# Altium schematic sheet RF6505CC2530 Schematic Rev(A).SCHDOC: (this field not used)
size D; Organization: (this field not used); Address1: (this field not used); Address2: (this field not used); Address3: (this field not used); Address4: (this field not used); DocumentNumber: (this field not used); Revision: (this field not used); SheetNumber: (this field not used); SheetTotal: (this field not used); Date: (this field not used); ApprovedBy: (this field not used); CheckedBy: (this field not used); Author: (this field not used); CompanyName: (this field not used); DrawnBy: (this field not used); Engineer: (this field not used); AFamilypn: 6505; PageSetup: Record=PageOptions|CenterHorizontal=True|CenterVertical=True|PrintScale=0.51|XCorrection=1.00|YCorrection=1.00|PrintKind=0|BorderSize=5000000|LeftOffset=0|BottomOffset=0|Orientation=2|PaperLength=1000|PaperWidth=1000|Scale=100|PaperSource=7|PrintQuality=600|MediaType=1|DitherType=10|PaperKind=11" x 17"|PrintScaleMode=1; Apcbpartnumber: 6505-411; Atitle: RF6505CC2530410 Eval Schem.; Adocumentnumber: 6505-401; Apagenumber: 1; Apagenumbertotal: 1; Arevision: A; Adrawnby: Michael Coolen; Adate: 07/26/11
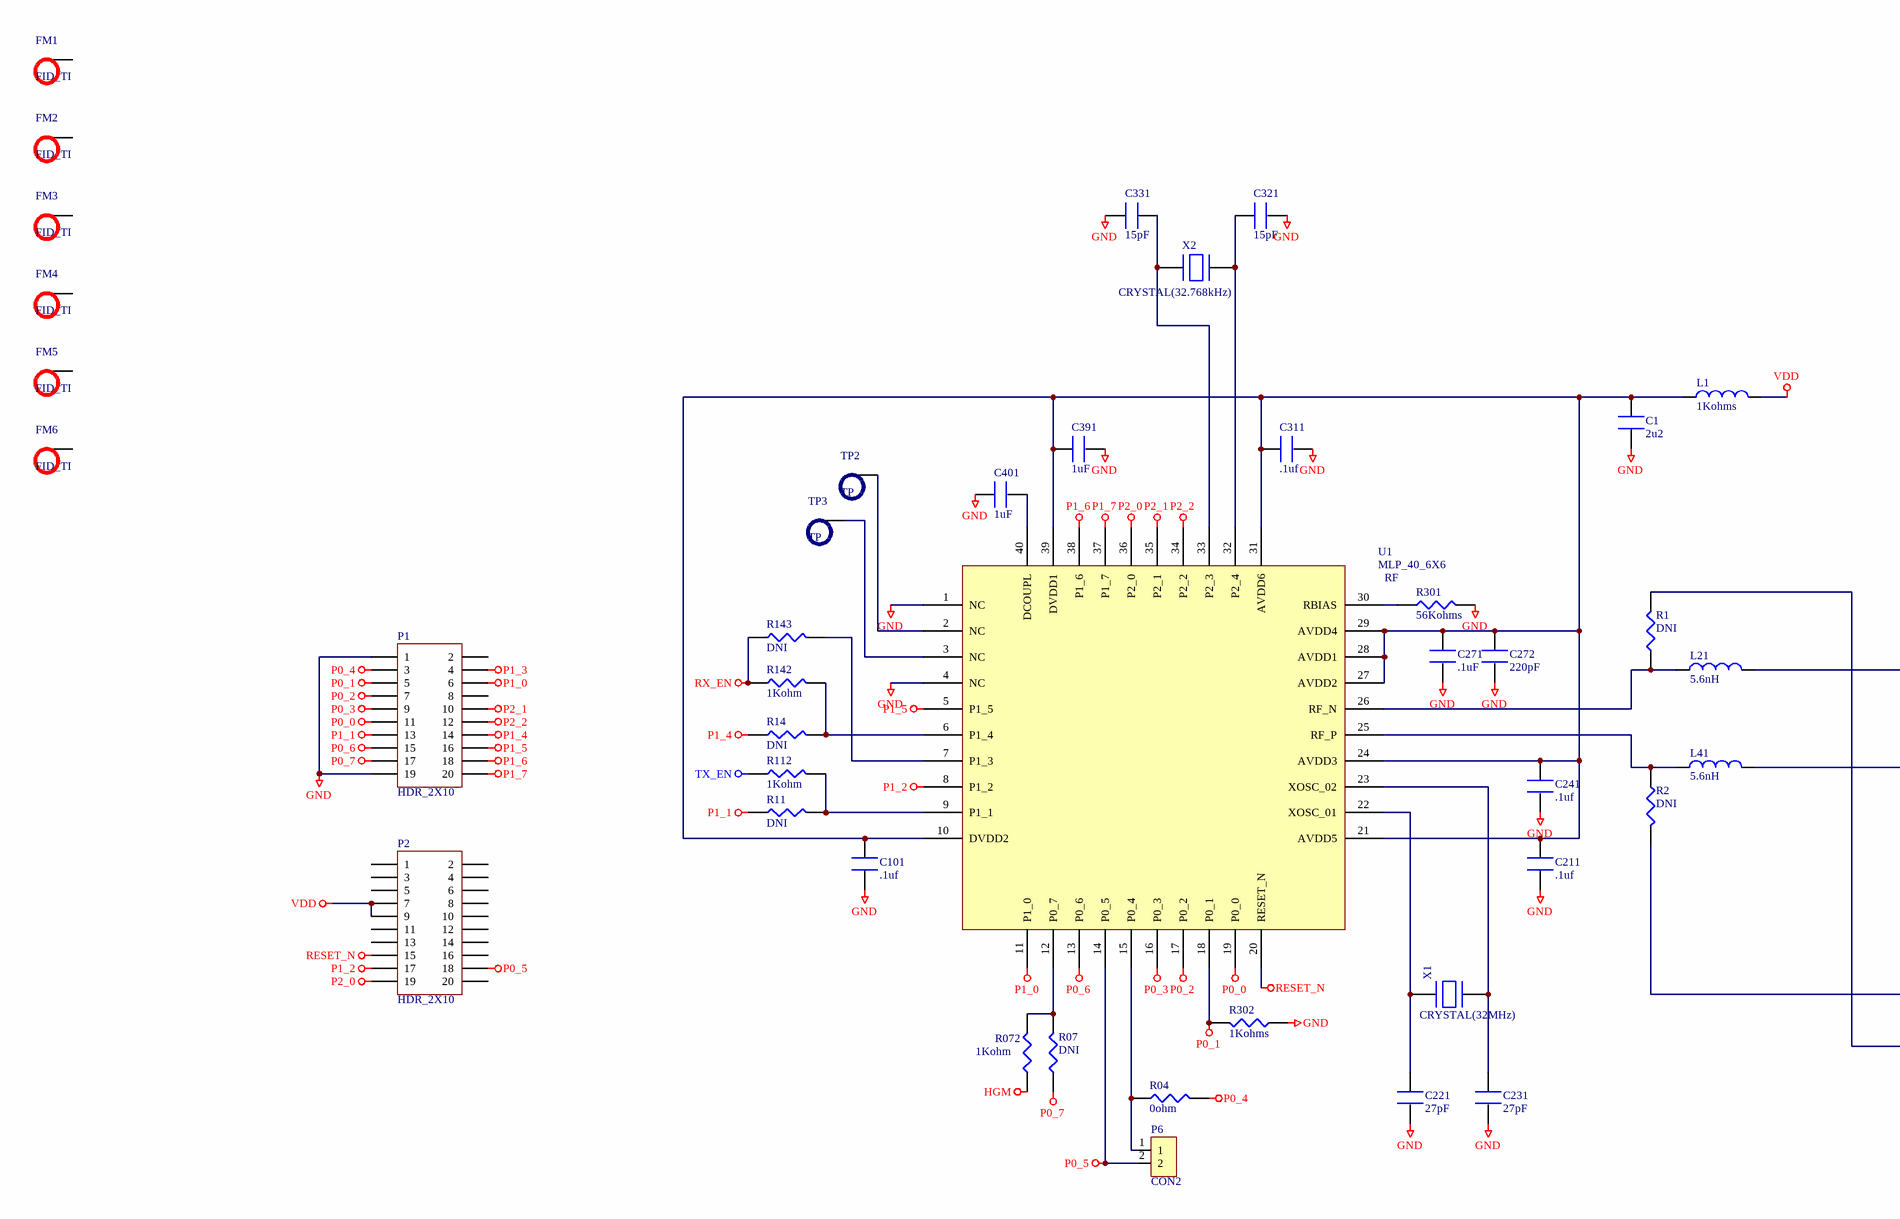
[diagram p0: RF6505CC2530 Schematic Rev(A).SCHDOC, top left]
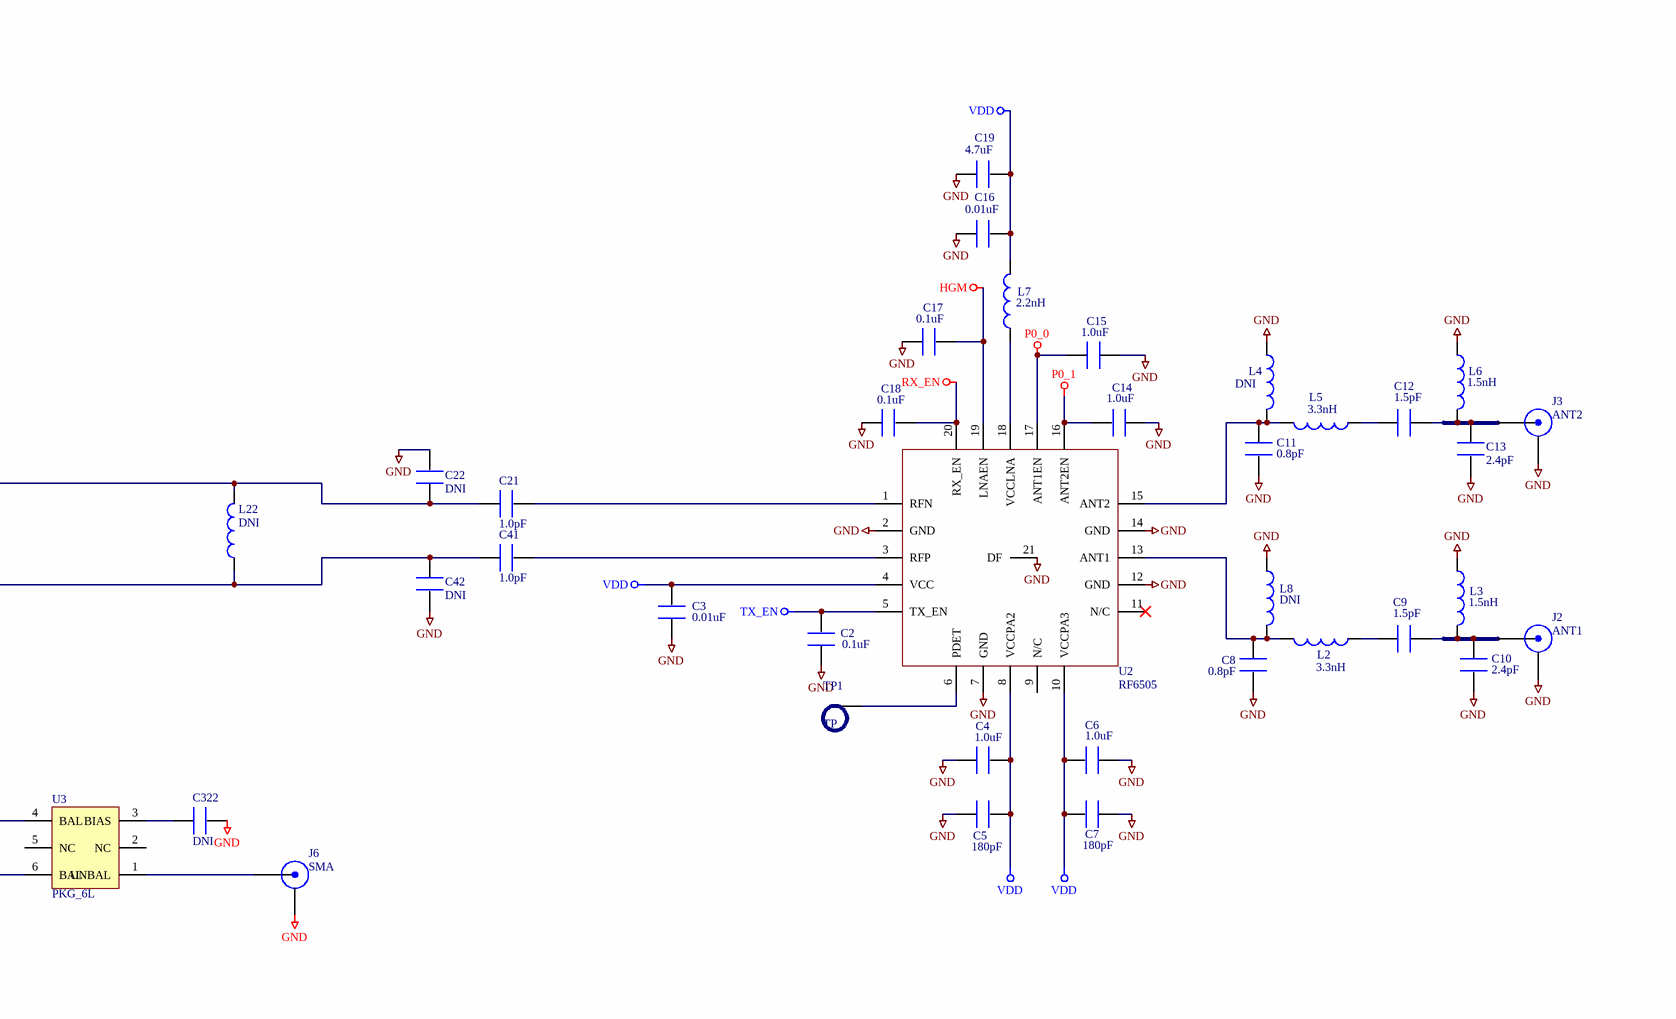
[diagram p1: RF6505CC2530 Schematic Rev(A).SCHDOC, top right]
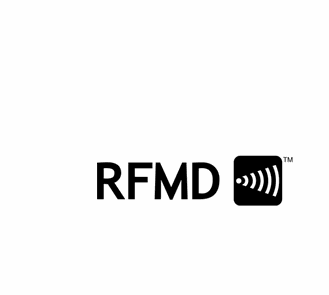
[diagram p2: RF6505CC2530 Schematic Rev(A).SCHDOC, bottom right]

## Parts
C1  2u2  [0402_TI]
C2  0.1uF  [0402(A)]
C3  0.01uF  [0402(A)]
C4  1.0uF  [0402(A)]
C5  180pF  [0402(A)]
C6  1.0uF  [0402(A)]
C7  180pF  [0402(A)]
C8  0.8pF  [0402(A)]
C9  1.5pF  [0402(A)]
C10  2.4pF  [0402(A)]
C11  0.8pF  [0402(A)]
C12  1.5pF  [0402(A)]
C13  2.4pF  [0402(A)]
C14  1.0uF  [0402(A)]
C15  1.0uF  [0402(A)]
C16  0.01uF  [0402(A)]
C17  0.1uF  [0402(A)]
C18  0.1uF  [0402(A)]
C19  4.7uF  [0603(A)]
C21  1.0pF  [0402_T1_2]
C22  DNI  [0402_T1_2]
C41  1.0pF  [0402_T1_2]
C42  DNI  [0402_T1_2]
C101  .1uf  [0402_TI]
C211  .1uf  [0402_TI]
C221  27pF  [0402_TI]
C231  27pF  [0402_TI]
C241  .1uf  [0402_TI]
C271  .1uF  [0402_TI]
C272  220pF  [0402_TI]
C311  .1uf  [0402_TI]
C321  15pF  [0402_TI]
C322  DNI  [0402_T1_2]
C331  15pF  [0402_TI]
C391  1uF  [0402_TI]
C401  1uF  [0402_TI]
FM1  FID_TI  [FID_TI]
FM2  FID_TI  [FID_TI]
FM3  FID_TI  [FID_TI]
FM4  FID_TI  [FID_TI]
FM5  FID_TI  [FID_TI]
FM6  FID_TI  [FID_TI]
J2  ANT1  [SMA_008_MABDC_G1_VIPER]
J3  ANT2  [SMA_008_MABDC_G1_VIPER]
J6  SMA  [SMA_008_MABDC_G1_VIPER_BS]
L1  1Kohms  [INDC1005AL]
L2  3.3nH  [0402(A)]
L3  1.5nH  [0402(A)]
L4  DNI  [0402(A)]
L5  3.3nH  [0402(A)]
L6  1.5nH  [0402(A)]
L7  2.2nH  [0402(A)]
L8  DNI  [0402(A)]
L21  5.6nH  [0402_S]
L22  DNI  [0402_T1_2]
L41  5.6nH  [0402_S]
LOGO  RFMDLOGO  [RFMD_LOGO]  (value not drawn)
P1  HDR_2X10  [20PIN_SM]
P2  HDR_2X10  [20PIN_SM]
P6  CON2  [PINROW_1X2]
R1  DNI  [0402_S]
R2  DNI  [0402_S]
R04  0ohm  [0402_T1_2]
R07  DNI  [0402_TI]
R11  DNI  [0402_TI]
R14  DNI  [0402_TI]
R072  1Kohm  [0402_TI]
R112  1Kohm  [0402_TI]
R142  1Kohm  [0402_TI]
R143  DNI  [0402_TI]
R301  56Kohms  [0402_TI]
R302  1Kohms  [0402_S]
TP1  TP  [TP]
TP2  TP  [TP]
TP3  TP  [TP]
U1  MLP_40_6X6  Comment_2: RF  [CC2530]
U2  RF6505  [3.5x3.5 20 pin]
U3  PKG_6L  [LDB182]
X1  CRYSTAL(32MHz)  [CRYSTAL_24-54]
X2  CRYSTAL(32.768kHz)  [CRYSTAL_32.768]

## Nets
GND: C1.2 C2.1 C3.1 C4.1 C5.1 C6.1 C7.1 C8.2 C10.2 C11.2 C13.2 C14.1 C15.1 C16.1 C17.1 C18.1 C19.1 C22.2 C42.2 C101.2 C211.2 C221.2 C231.2 C241.2 C271.2 C272.2 C311.2 C321.2 C322.2 C331.2 C391.2 C401.1 J2.2(GND) J2.3(GND) J2.4(GND) J2.5(GND) J2.6(GND) J2.7(GND) J2.8(GND) J2.9(GND) J3.2(GND) J3.3(GND) J3.4(GND) J3.5(GND) J3.6(GND) J3.7(GND) J3.8(GND) J3.9(GND) J6.2(GND) J6.3(GND) J6.4(GND) J6.5(GND) J6.6(GND) J6.7(GND) J6.8(GND) J6.9(GND) L3.2 L4.2 L6.2 L8.2 P1.1 P1.19 R301.2 R302.1 U1.1(NC) U1.4(NC) U1.41(GND) U2.2(GND) U2.7(GND) U2.12(GND) U2.14(GND) U2.21(DF) X1.2 X1.4
HGM: C17.2 R072.1 U2.19(LNAEN)
P0_0: C15.2 P1.11 U1.19(P0_0) U2.17(ANT1EN)
P0_1: C14.2 P1.5 R302.2 U1.18(P0_1) U2.16(ANT2EN)
P0_2: P1.7 U1.17(P0_2)
P0_3: P1.9 U1.16(P0_3)
P0_4: P1.3 R04.2
P0_5: P2.18 P6.2 U1.14(P0_5)
P0_6: P1.15 U1.13(P0_6)
P0_7: P1.17 R07.1
P1_0: P1.6 U1.11(P1_0)
P1_1: P1.13 R11.1
P1_2: P2.17 U1.8(P1_2)
P1_3: P1.4
P1_4: P1.14 R14.1
P1_5: P1.16 U1.5(P1_5)
P1_6: P1.18 U1.38(P1_6)
P1_7: P1.20 U1.37(P1_7)
P2_0: P2.19 U1.36(P2_0)
P2_1: P1.10 U1.35(P2_1)
P2_2: P1.12 U1.34(P2_2)
RESET_N: P2.15 U1.20(RESET_N)
RX_EN: C18.2 R142.1 R143.1 U2.20(RX_EN)
TX_EN: C2.2 R112.1 U2.5(TX_EN)
VDD: C3.2 C4.2 C5.2 C6.2 C7.2 C16.2 C19.2 L1.1 L7.2 P2.7 P2.9 U2.4(VCC) U2.8(VCCPA2) U2.10(VCCPA3)
NetC1_1: C1.1 C101.1 C211.1 C241.1 C271.1 C272.1 C311.1 C391.1 L1.2 U1.10(DVDD2) U1.21(AVDD5) U1.24(AVDD3) U1.27(AVDD2) U1.28(AVDD1) U1.29(AVDD4) U1.31(AVDD6) U1.39(DVDD1)
NetC8_1: C8.1 L2.2 L8.1 U2.13(ANT1)
NetC9_1: C9.1 L2.1
NetC9_2: C9.2 C10.1 J2.1(I/O) L3.1
NetC11_1: C11.1 L4.1 L5.2 U2.15(ANT2)
NetC12_1: C12.1 L5.1
NetC12_2: C12.2 C13.1 J3.1(I/O) L6.1
NetC21_1: C21.1 C22.1 L21.2 L22.2
NetC21_2: C21.2 U2.1(RFN)
NetC41_1: C41.1 C42.1 L22.1 L41.2
NetC41_2: C41.2 U2.3(RFP)
NetC221_1: C221.1 U1.22(XOSC_01) X1.1
NetC231_1: C231.1 U1.23(XOSC_02) X1.3
NetC321_1: C321.1 U1.32(P2_4) X2.2
NetC322_1: C322.1 U3.3(BIAS)
NetC331_1: C331.1 U1.33(P2_3) X2.1
NetC401_2: C401.2 U1.40(DCOUPL)
NetJ6_1: J6.1(I/O) U3.1(UNBAL)
NetL7_1: L7.1 U2.18(VCCLNA)
NetL21_1: L21.1 R1.1 U1.26(RF_N)
NetL41_1: L41.1 R2.1 U1.25(RF_P)
NetP6_1: P6.1 R04.1 U1.15(P0_4)
NetR1_2: R1.2 U3.6(BAL)
NetR2_2: R2.2 U3.4(BAL)
NetR07_2: R07.2 R072.2 U1.12(P0_7)
NetR11_2: R11.2 R112.2 U1.9(P1_1)
NetR14_2: R14.2 R142.2 U1.6(P1_4)
NetR143_2: R143.2 U1.7(P1_3)
NetR301_1: R301.1 U1.30(RBIAS)
NetTP1_1: TP1.1 U2.6(PDET)
NetTP2_1: TP2.1 U1.2(NC)
NetTP3_1: TP3.1 U1.3(NC)

Not connected (* = marked no-connect by the designer): FM1 1(0); FM2 1(0); FM3 1(0); FM4 1(0); FM5 1(0); FM6 1(0); P1 2 8; P2 1 2 3 4 5 6 8 10 11 12 13 14 16 20; U2 9(N/C) 11(N/C)*; U3 2(NC) 5(NC); X2 3 4

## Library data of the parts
C1-C19 C21 C22 C41 C42 C101 C211 C221 C231 C241 C271 C272 C311 C321 C322 C331 C391 C401 = CAPACITOR(A): Capacitor
J2 J3 J6 = SMA_008: SMA Connector
L1 = Inductor: Code_IEC: 1005
L2-L8 L21 L22 L41 = INDUCTOR(A): Inductor
LOGO = RFMDLOGO: RFMD LOGO
P6 = CON2: 2 PIN HEADER
R1 R2 R04 R07 R11 R14 R072 R112 R142 R143 R301 R302 = RESISTOR(A): Resistor
U1 = MLP_40_6X6: MLP 40 6X6
U2 = 20-LEAD RF6505
X1 = CRYSTAL(A) Epson: CRYSTAL
X2 = CRYSTAL(A): CRYSTAL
